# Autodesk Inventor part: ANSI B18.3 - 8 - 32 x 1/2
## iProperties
IsCustomPart: 0
Created: 2008-02
Part Number: ANSI B18.3 - 8 - 32 x 1/2
Material: Steel, Mild
Description: Hexagon Socket Button Head Cap Screw
Document SubType Name: Modeling
Standard: ANSI B18.3
Standard Revision: 2003
Standards Organization: ANSI
Language: en-US
Size Designation: 8 - 32 x 1/2
Categories: <MemberInstance><Categories><Category DisplayName="Fasteners" InternalName="e4da775c-781d-43d5-af7c-5136215cf5a6" Mnemonic="FSTN"><Category DisplayName="Bolts"
Density: 1 g/cm^3
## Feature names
1. Body [Revolution]
2. Slot [Extrusion]
3. Fillet1
4. Chamfer1
5. Fillet2
